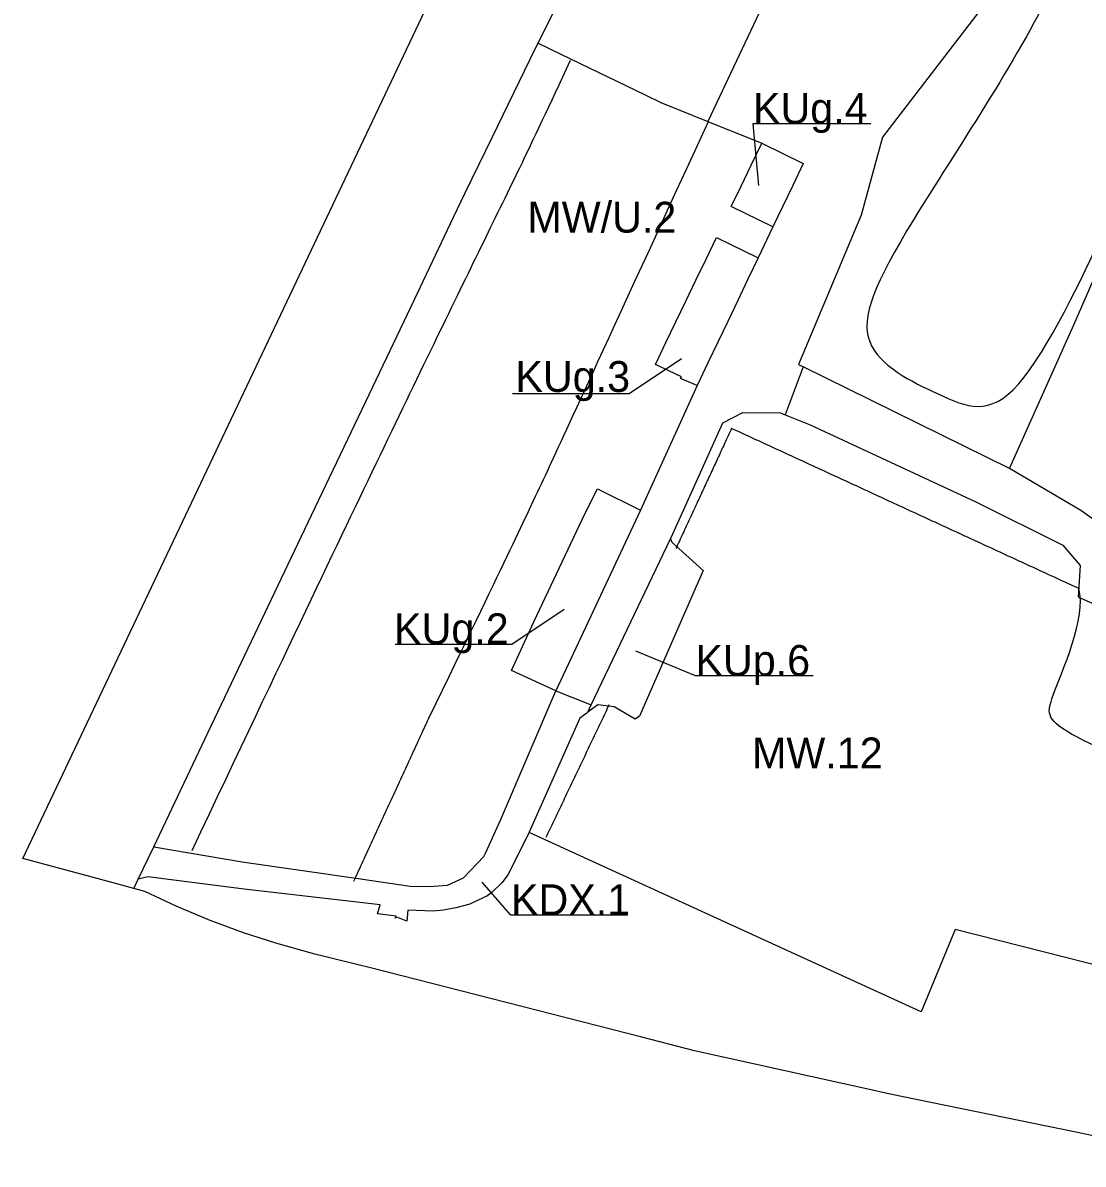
# Model space of a CAD drawing. Extents: x 7424788 to 7425732, y 5549810 to 5550591.
# Drawn here: x 7424904.1 to 7425041.7, y 5549883.4 to 5550031.4 of the extents above; entities that cross this region are included whole.
import ezdxf

# ---------------------------------------------------------------- set-up
doc = ezdxf.new("R2010")
doc.units = 0
for name, color, linetype in [('WIL_granica obszaru objętego planem', 7, 'Continuous'), ('WIL_linia rozgraniczające tereny o różnym przeznaczeniu lub różnych zasadach zagospodarowania', 7, 'Continuous'), ('WIL_linia rozgraniczające tereny o różnym przeznaczeniu lub różnych zasadach zagospodarowania_OPISY', 7, 'Continuous'), ('WIL_nieprzekraczalne linie zabudowy', 7, 'Continuous')]:
    doc.layers.add(name, color=color, linetype=linetype)

msp = doc.modelspace()

# ---------------------------------------------------------------- linework, layer by layer
at = {"layer": 'WIL_granica obszaru objętego planem'}
for p, q in [((7424904.13, 5549923.06), (7425177.26, 5550499.06)), ((7424904.13, 5549923.06), (7424904.13, 5549923.06)), ((7424915.36, 5549920.01), (7424904.13, 5549923.06)), ((7424991.24, 5549898.12), (7424984.42, 5549899.87)), ((7425014.34, 5549892.99), (7424991.24, 5549898.12)), ((7425015.86, 5549892.66), (7425014.34, 5549892.99)), ((7425060.24, 5549883.4), (7425040.93, 5549887.52))]:
    msp.add_line(p, q, dxfattribs=at)
for points in [[(7424919.96, 5549918.77), (7424918.52, 5549919.16), (7424915.36, 5549920.01)], [(7424928.41, 5549915), (7424924.03, 5549916.86), (7424919.96, 5549918.77)], [(7424947.27, 5549909.36), (7424941.99, 5549910.63), (7424936.93, 5549912.07), (7424932.76, 5549913.41), (7424928.41, 5549915)], [(7424984.42, 5549899.87), (7424949.4, 5549908.84), (7424947.27, 5549909.36)], [(7425040.93, 5549887.52), (7425018.1, 5549892.16), (7425015.86, 5549892.66)]]:
    msp.add_lwpolyline(points, dxfattribs=at)
at = {"layer": 'WIL_linia rozgraniczające tereny o różnym przeznaczeniu lub różnych zasadach zagospodarowania'}
for p, q in [((7424904.13, 5549923.06), (7425177.26, 5550499.06)), ((7425037.02, 5550044.53), (7425015.64, 5550016.61)), ((7424970.95, 5550028.81), (7424975.91, 5550038.84)), ((7424999.62, 5550032.75), (7424992.99, 5550018.64)), ((7424965.03, 5550016.67), (7424970.59, 5550028.08)), ((7424970.59, 5550028.08), (7424970.95, 5550028.81)), ((7424970.95, 5550028.81), (7424975.15, 5550026.78)), ((7424975.15, 5550026.78), (7424984.83, 5550022.1)), ((7424984.83, 5550022.1), (7424986.89, 5550021.1)), ((7424986.89, 5550021.1), (7424992.99, 5550018.64)), ((7424992.99, 5550018.64), (7424999.97, 5550015.82)), ((7424961.48, 5550009.39), (7424965.03, 5550016.67)), ((7425015.64, 5550016.61), (7425012.87, 5550006.51)), ((7424998.6, 5550012.96), (7424999.97, 5550015.82)), ((7424999.97, 5550015.82), (7425005.36, 5550013.19)), ((7425005.36, 5550013.19), (7425004, 5550010.34)), ((7424997.3, 5550010.27), (7424998.6, 5550012.96)), ((7424996.02, 5550007.6), (7424997.3, 5550010.27)), ((7425004, 5550010.34), (7425002.7, 5550007.65)), ((7424959.98, 5550006.22), (7424961.48, 5550009.39)), ((7425001.42, 5550004.97), (7424996.02, 5550007.6)), ((7425002.7, 5550007.65), (7425001.42, 5550004.97)), ((7424954.94, 5549995.56), (7424959.98, 5550006.22)), ((7425012.87, 5550006.51), (7425004.75, 5549987.11)), ((7425001.42, 5550004.97), (7424999.51, 5550000.98)), ((7424992.71, 5550000.72), (7424994.1, 5550003.61)), ((7424994.1, 5550003.61), (7424999.51, 5550000.98)), ((7424991.42, 5549998.05), (7424992.71, 5550000.72)), ((7424999.51, 5550000.98), (7424998.13, 5549998.09)), ((7425040.46, 5549992.28), (7425043.54, 5549999.42)), ((7424990.13, 5549995.36), (7424991.42, 5549998.05)), ((7424998.13, 5549998.09), (7424996.85, 5549995.41)), ((7424948.63, 5549982.33), (7424954.94, 5549995.56)), ((7424988.83, 5549992.66), (7424990.13, 5549995.36)), ((7424996.85, 5549995.41), (7424995.56, 5549992.72)), ((7424987.54, 5549989.97), (7424988.83, 5549992.66)), ((7424995.56, 5549992.72), (7424994.26, 5549990.01)), ((7425032.09, 5549973.63), (7425040.46, 5549992.28)), ((7424986.18, 5549987.14), (7424987.54, 5549989.97)), ((7424994.26, 5549990.01), (7424992.98, 5549987.33)), ((7424989.54, 5549985.52), (7424986.18, 5549987.14)), ((7424992.98, 5549987.33), (7424991.62, 5549984.5)), ((7425005.34, 5549986.82), (7425003.01, 5549980.61)), ((7425004.75, 5549987.11), (7425005.34, 5549986.82)), ((7425032.09, 5549973.63), (7425005.34, 5549986.82)), ((7424989.43, 5549985.3), (7424989.54, 5549985.52)), ((7424991.57, 5549984.38), (7424989.43, 5549985.3)), ((7424991.57, 5549984.38), (7424984.26, 5549968.22)), ((7424991.62, 5549984.5), (7424991.57, 5549984.38)), ((7424941.59, 5549967.57), (7424948.63, 5549982.33)), ((7424994.94, 5549979.54), (7424997.53, 5549980.92)), ((7424997.53, 5549980.92), (7425002.42, 5549980.85)), ((7425002.42, 5549980.85), (7425003.01, 5549980.61)), ((7425003.01, 5549980.61), (7425006.25, 5549979.28)), ((7424991.46, 5549971.88), (7424994.94, 5549979.54)), ((7425006.25, 5549979.28), (7425027.75, 5549969.31)), ((7425041.35, 5549968.17), (7425032.09, 5549973.63)), ((7424988.42, 5549965.15), (7424991.46, 5549971.88)), ((7424977.05, 5549967.83), (7424978.66, 5549971)), ((7424978.66, 5549971), (7424984.26, 5549968.22)), ((7425027.75, 5549969.31), (7425039.03, 5549963.68)), ((7424934.23, 5549952.13), (7424941.59, 5549967.57)), ((7424970.42, 5549953.73), (7424977.05, 5549967.83)), ((7424984.26, 5549968.22), (7424973.24, 5549944.81)), ((7425042.87, 5549967.11), (7425041.35, 5549968.17)), ((7424977.85, 5549942.97), (7424988.12, 5549964.52)), ((7424988.12, 5549964.52), (7424988.42, 5549965.15)), ((7424988.12, 5549964.52), (7424988.29, 5549964.07)), ((7424988.29, 5549964.07), (7424992.36, 5549960.4)), ((7425039.03, 5549963.68), (7425041.25, 5549961.05)), ((7424992.36, 5549960.4), (7424984.1, 5549941.52)), ((7425041.25, 5549961.05), (7425040.99, 5549956.99)), ((7425040.99, 5549956.99), (7425041.35, 5549956.83)), ((7425041.35, 5549956.83), (7425045.15, 5549955.11)), ((7424967.52, 5549947.45), (7424970.42, 5549953.73)), ((7424928.17, 5549939.43), (7424934.23, 5549952.13)), ((7424973.24, 5549944.81), (7424967.52, 5549947.45)), ((7424966.07, 5549928.01), (7424973.24, 5549944.81)), ((7424973.24, 5549944.81), (7424977.85, 5549942.97)), ((7424977.4, 5549942.01), (7424977.85, 5549942.97)), ((7424978.72, 5549942.96), (7424977.4, 5549942.01)), ((7424980.82, 5549942.7), (7424978.72, 5549942.96)), ((7424983.57, 5549941.13), (7424980.82, 5549942.7)), ((7424976.36, 5549941.26), (7424969.81, 5549926.45)), ((7424976.83, 5549941.6), (7424976.36, 5549941.26)), ((7424977.27, 5549941.92), (7424976.83, 5549941.6)), ((7424977.4, 5549942.01), (7424977.27, 5549941.92)), ((7424984.1, 5549941.52), (7424983.57, 5549941.13)), ((7424921.1, 5549924.58), (7424928.17, 5549939.43)), ((7424964.18, 5549923.84), (7424966.07, 5549928.01)), ((7424969.78, 5549926.4), (7424967.05, 5549920.94)), ((7424969.81, 5549926.45), (7424969.78, 5549926.4)), ((7425020.63, 5549903.15), (7424969.78, 5549926.4)), ((7424919.09, 5549920.35), (7424921.1, 5549924.58)), ((7424921.1, 5549924.58), (7424932.56, 5549922.6)), ((7424904.13, 5549923.06), (7424904.13, 5549923.06)), ((7424915.36, 5549920.01), (7424904.13, 5549923.06)), ((7424961.29, 5549920.52), (7424963.93, 5549923.3)), ((7424963.93, 5549923.3), (7424964.18, 5549923.84)), ((7424932.56, 5549922.6), (7424947.91, 5549920.42)), ((7424918.52, 5549919.16), (7424919.09, 5549920.35)), ((7424920.35, 5549920.67), (7424919.09, 5549920.35)), ((7424932.85, 5549919.08), (7424920.35, 5549920.67)), ((7424947.91, 5549920.42), (7424954.37, 5549919.48)), ((7424959.22, 5549919.61), (7424961.29, 5549920.52)), ((7424966.28, 5549919.92), (7424964.96, 5549918.62)), ((7424967.05, 5549920.94), (7424966.28, 5549919.92)), ((7424950.47, 5549917.06), (7424932.85, 5549919.08)), ((7424954.37, 5549919.48), (7424956.89, 5549919.41)), ((7424956.89, 5549919.41), (7424959.22, 5549919.61)), ((7424964.96, 5549918.62), (7424964.31, 5549918.16)), ((7424950.13, 5549915.89), (7424950.47, 5549917.06)), ((7424962.11, 5549917.14), (7424960.3, 5549916.65)), ((7424962.55, 5549917.33), (7424962.11, 5549917.14)), ((7424963.77, 5549917.92), (7424962.55, 5549917.33)), ((7424963.78, 5549917.93), (7424963.77, 5549917.92)), ((7424964.31, 5549918.16), (7424963.78, 5549917.93)), ((7424952.55, 5549915.58), (7424950.13, 5549915.89)), ((7424952.42, 5549915.3), (7424952.55, 5549915.58)), ((7424952.63, 5549915.43), (7424952.42, 5549915.3)), ((7424953.94, 5549914.91), (7424952.63, 5549915.43)), ((7424954.08, 5549916.35), (7424953.94, 5549914.91)), ((7424957.35, 5549916.22), (7424954.08, 5549916.35)), ((7424958.7, 5549916.35), (7424957.35, 5549916.22)), ((7424960.3, 5549916.65), (7424958.7, 5549916.35)), ((7425025.04, 5549913.83), (7425020.63, 5549903.15)), ((7425067.94, 5549902.95), (7425025.04, 5549913.83)), ((7424991.24, 5549898.12), (7424984.42, 5549899.87)), ((7425014.34, 5549892.99), (7424991.24, 5549898.12)), ((7425015.86, 5549892.66), (7425014.34, 5549892.99)), ((7425060.24, 5549883.4), (7425040.93, 5549887.52))]:
    msp.add_line(p, q, dxfattribs=at)
for points in [[(7424919.96, 5549918.77), (7424918.52, 5549919.16), (7424915.36, 5549920.01)], [(7424928.41, 5549915), (7424924.03, 5549916.86), (7424919.96, 5549918.77)], [(7424947.27, 5549909.36), (7424941.99, 5549910.63), (7424936.93, 5549912.07), (7424932.76, 5549913.41), (7424928.41, 5549915)], [(7424984.42, 5549899.87), (7424949.4, 5549908.84), (7424947.27, 5549909.36)], [(7425040.93, 5549887.52), (7425018.1, 5549892.16), (7425015.86, 5549892.66)]]:
    msp.add_lwpolyline(points, dxfattribs=at)
at = {"layer": 'WIL_linia rozgraniczające tereny o różnym przeznaczeniu lub różnych zasadach zagospodarowania_OPISY'}
for points in [[(7425014.11, 5550018.35), (7424998.83, 5550018.35), (7424999.56, 5550010.36)], [(7424967.65, 5549983.37), (7424982.77, 5549983.37), (7424989.57, 5549987.92)], [(7424952.42, 5549950.85), (7424967.54, 5549950.85), (7424974.33, 5549955.4)], [(7425006.64, 5549946.74), (7424991.37, 5549946.74), (7424983.65, 5549949.94)], [(7424982.57, 5549915.7), (7424967.44, 5549915.7), (7424963.69, 5549919.96)]]:
    msp.add_lwpolyline(points, dxfattribs=at)
at = {"layer": 'WIL_nieprzekraczalne linie zabudowy'}
for points, degree in [([(7425084, 5550116.97), (7425064.39, 5550084.82), (7425059.12, 5550086.67), (7425051.28, 5550078.98), (7425041.03, 5550054.98), (7425041.88, 5550039.52), (7425016.38, 5550001.91), (7425010.97, 5549988.95), (7425023.53, 5549982.92), (7425032.48, 5549978.98), (7425046.3, 5550008.75), (7425046.87, 5550009.18), (7425051.43, 5550006.76), (7425080.91, 5549993.79), (7425114.24, 5549978.91), (7425118.94, 5549976.91), (7425119.45, 5549978.1), (7425161.39, 5549959.96), (7425169.94, 5549978.62), (7425122.22, 5550000.85), (7425121.22, 5549998.57), (7425055.13, 5550028.34), (7425049.86, 5550030.83), (7425059.26, 5550053.19), (7425084.9, 5550042.08), (7425096.96, 5550036.41), (7425124.07, 5550078.83)], 3), ([(7424975.13, 5550026.55), (7424969.57, 5550014.62), (7424964.37, 5550004.1), (7424951.61, 5549977.87), (7424938.38, 5549950.1), (7424926.03, 5549924.05)], 3), ([(7424956.78, 5549941.24), (7424966.72, 5549961.66), (7424971.15, 5549971.1), (7424977.55, 5549984.9), (7424993, 5550018.54)], 3), ([(7424996.05, 5549978.83), (7424988.83, 5549963.25)], 1), ([(7425041.09, 5549958.06), (7424996.05, 5549978.83)], 1), ([(7425068.94, 5549927.44), (7425037.04, 5549939.67), (7425035.61, 5549940.52), (7425042.17, 5549954.34), (7425041.09, 5549958.06)], 3), ([(7424980.15, 5549942.97), (7424971.98, 5549925.78)], 1), ([(7424947.07, 5549920.12), (7424956.78, 5549941.24)], 1)]:
    msp.add_open_spline(points, degree=degree, dxfattribs=at)

# ---------------------------------------------------------------- texts
at = {"layer": 'WIL_linia rozgraniczające tereny o różnym przeznaczeniu lub różnych zasadach zagospodarowania_OPISY'}
for s, p in [('KUg.4', (7424998.83, 5550018.35)), ('MW/U.2', (7424969.57, 5550004.23)), ('KUg.3', (7424968.02, 5549983.57)), ('KUg.2', (7424952.28, 5549950.85)), ('KUp.6', (7424991.37, 5549946.74)), ('MW.12', (7424998.71, 5549934.74)), ('KDX.1', (7424967.44, 5549915.7))]:
    msp.add_text(s, height=4, dxfattribs=at).set_placement(p)

doc.saveas('drawing.dxf')
